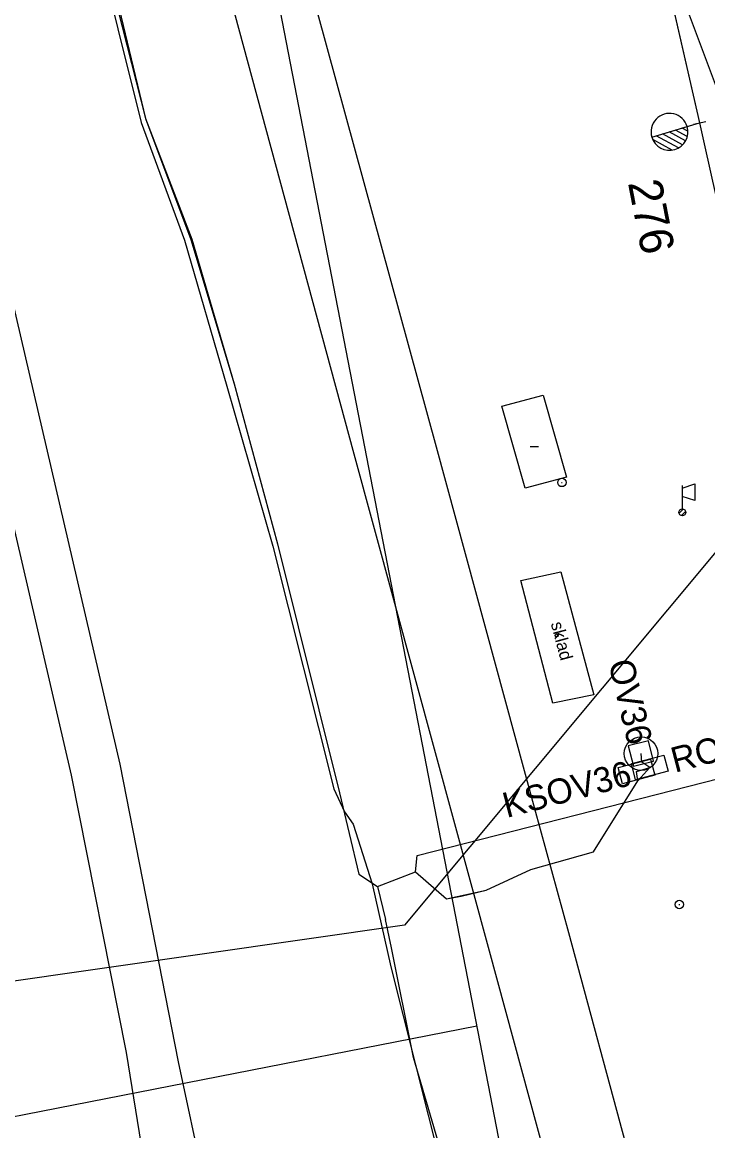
# Model space of a CAD drawing. Extents: x -545846 to -545044, y -1122650 to -1119108.
# Drawn here: x -545637 to -545596.2, y -1119489.2 to -1119423.2 of the extents above; entities that cross this region are included whole.
import ezdxf

# ---------------------------------------------------------------- set-up
doc = ezdxf.new("R2010")
doc.units = 0
for name, color, linetype in [('osvětlené plochy-hodnota-obrys', 7, 'Continuous'), ('Vrstva 1', 7, 'Continuous'), ('Vrstva 12', 7, 'Continuous'), ('Vrstva 12 - Trakce zaklady', 7, 'Continuous'), ('Vrstva 2', 7, 'Continuous'), ('Vrstva 23', 7, 'Continuous'), ('Vrstva 25', 7, 'Continuous'), ('Vrstva 26', 7, 'Continuous'), ('Vrstva 28', 7, 'Continuous'), ('Vrstva 31', 7, 'Continuous'), ('Vrstva 33', 7, 'Continuous'), ('Vrstva 51', 7, 'Continuous'), ('Vrstva 59', 7, 'Continuous'), ('Vrstva 63', 7, 'Continuous')]:
    doc.layers.add(name, color=color, linetype=linetype)

msp = doc.modelspace()

# ---------------------------------------------------------------- linework, layer by layer
at = {"layer": 'osvětlené plochy-hodnota-obrys'}
for points in [[(-545584.854, -1119581.025), (-545603.392, -1119516.801), (-545628.868, -1119385.178)], [(-545609.939, -1119482.977), (-545646.431, -1119490.114), (-545644.897, -1119509.516)]]:
    msp.add_lwpolyline(points, dxfattribs=at)
at = {"layer": 'Vrstva 1'}
for points in [[(-545618.129, -1119370.039), (-545613.658, -1119380.515), (-545613.464, -1119380.986), (-545613.183, -1119381.639), (-545612.962, -1119382.15), (-545612.697, -1119382.765), (-545608.279, -1119393.257), (-545603.774, -1119405.466), (-545603.474, -1119406.246), (-545599.509, -1119416.895), (-545595.059, -1119428.818), (-545593.223, -1119433.873), (-545592.939, -1119434.643), (-545588.997, -1119445.3), (-545584.66, -1119457.036), (-545584.438, -1119457.631), (-545580.06, -1119469.458), (-545575.519, -1119480.71), (-545575.08, -1119481.827), (-545571.114, -1119492.526), (-545565.786, -1119504.472), (-545565.51, -1119505.15), (-545561.154, -1119515.645), (-545556.304, -1119527.336)], [(-545599.509, -1119416.895), (-545596.688, -1119429.205), (-545596.412, -1119430.453), (-545593.934, -1119441.543), (-545591.162, -1119453.963), (-545590.21, -1119458.416), (-545589.948, -1119459.646), (-545584.996, -1119483.934), (-545580.037, -1119509.486), (-545578.326, -1119518.28), (-545575.837, -1119531.038)], [(-545620.215, -1119419.861), (-545619.425, -1119422.675), (-545612.369, -1119448.498), (-545606.521, -1119470.008), (-545604.503, -1119477.399), (-545597.322, -1119503.974), (-545591.579, -1119526.224), (-545589.811, -1119534.529)], [(-545624.755, -1119421.279), (-545624.132, -1119423.572), (-545617.269, -1119448.911), (-545611.272, -1119470.899), (-545609.213, -1119478.484), (-545602.008, -1119504.992), (-545596.298, -1119527.379), (-545594.617, -1119534.889)]]:
    msp.add_lwpolyline(points, dxfattribs=at)
at = {"layer": 'Vrstva 12'}
msp.add_lwpolyline([(-545599.436, -1119467.19), (-545599.726, -1119465.996), (-545600.944, -1119466.286), (-545600.627, -1119467.504), (-545599.436, -1119467.19)], dxfattribs=at)
at = {"layer": 'Vrstva 12 - Trakce zaklady'}
msp.add_lwpolyline([(-545599.436, -1119467.19), (-545599.726, -1119465.996), (-545600.944, -1119466.286), (-545600.627, -1119467.504), (-545599.436, -1119467.19)], dxfattribs=at)
at = {"layer": 'Vrstva 2'}
for p, q in [((-545599.509, -1119416.895), (-545596.688, -1119429.205)), ((-545599.538, -1119430.057), (-545597.434, -1119429.43)), ((-545599.534, -1119430.063), (-545596.688, -1119429.205)), ((-545597.424, -1119430.013), (-545598.123, -1119429.636)), ((-545597.391, -1119429.707), (-545597.736, -1119429.52)), ((-545597.054, -1119429.287), (-545596.322, -1119429.123)), ((-545599.538, -1119430.058), (-545599.538, -1119430.057)), ((-545598.316, -1119430.827), (-545599.484, -1119430.195)), ((-545597.951, -1119430.7), (-545599.281, -1119429.981)), ((-545597.703, -1119430.51), (-545598.895, -1119429.865)), ((-545597.53, -1119430.279), (-545598.509, -1119429.75))]:
    msp.add_line(p, q, dxfattribs=at)
for points in [[(-545603.774, -1119405.466), (-545603.474, -1119406.246), (-545599.509, -1119416.895), (-545595.059, -1119428.818)], [(-545596.688, -1119429.205), (-545596.412, -1119430.453), (-545593.934, -1119441.543), (-545591.162, -1119453.963)]]:
    msp.add_lwpolyline(points, dxfattribs=at)
for centre, radius, start, end in [((-545598.485, -1119429.742), 1.097, 16.55021, 197.01973), ((-545598.485, -1119429.744), 1.098, 196.63974, 16.60059)]:
    msp.add_arc(centre, radius, start, end, dxfattribs=at)
at = {"layer": 'Vrstva 23'}
for points in [[(-545608.452, -1119446.078), (-545605.992, -1119445.422), (-545604.612, -1119450.286), (-545607.07, -1119450.954)], [(-545607.333, -1119456.452), (-545604.947, -1119455.922), (-545602.988, -1119463.245), (-545605.432, -1119463.739)]]:
    msp.add_lwpolyline(points, close=True, dxfattribs=at)
at = {"layer": 'Vrstva 25'}
for points in [[(-545599.611, -1119467.072), (-545599.356, -1119468.039), (-545601.289, -1119468.548), (-545601.544, -1119467.581), (-545599.611, -1119467.072)], [(-545600.499, -1119468.308), (-545600.754, -1119467.341), (-545598.821, -1119466.832), (-545598.566, -1119467.799), (-545600.499, -1119468.308)]]:
    msp.add_lwpolyline(points, dxfattribs=at)
msp.add_circle((-545600.175, -1119466.747), 1, dxfattribs=at)
at = {"layer": 'Vrstva 26'}
for points in [[(-545637.892, -1119393.614), (-545637.617, -1119393.956), (-545636.118, -1119401.068), (-545636.223, -1119402.773), (-545634.694, -1119408.722), (-545634.158, -1119410.258), (-545632.448, -1119418.009), (-545629.669, -1119428.958), (-545626.903, -1119436.124), (-545624.39, -1119444.734), (-545621.805, -1119454.265), (-545618.119, -1119469.086), (-545616.969, -1119473.918), (-545615.854, -1119474.651), (-545615.38, -1119476.622)], [(-545613.606, -1119473.785), (-545613.502, -1119472.802), (-545577.432, -1119463.601), (-545557.746, -1119458.579), (-545557.446, -1119459.448), (-545554.375, -1119463.212), (-545544.393, -1119474.38), (-545535.107, -1119485.279), (-545535.188, -1119486.544), (-545534.523, -1119485.978), (-545528.126, -1119494.269)], [(-545613.502, -1119472.802), (-545577.432, -1119463.601), (-545557.746, -1119458.579)], [(-545615.854, -1119474.651), (-545613.606, -1119473.785), (-545611.748, -1119475.391), (-545610.875, -1119475.225), (-545609.387, -1119474.874), (-545606.731, -1119473.65), (-545603.013, -1119472.594), (-545600.37, -1119468.37), (-545600.45, -1119467.81), (-545599.66, -1119467.57), (-545600.12, -1119467.25), (-545600.175, -1119466.747)], [(-545611.748, -1119475.391), (-545610.875, -1119475.225), (-545609.387, -1119474.874), (-545606.731, -1119473.65), (-545603.013, -1119472.594)], [(-545593.58, -1119580.619), (-545593.117, -1119579.157), (-545592.856, -1119575.399), (-545594.547, -1119566.647), (-545596.344, -1119556.09), (-545599.079, -1119544.096), (-545601.733, -1119531.043), (-545604.88, -1119521.254), (-545606.986, -1119511.352), (-545609.247, -1119502.752), (-545611.596, -1119492.082), (-545613.722, -1119484.832), (-545615.024, -1119478.308), (-545615.38, -1119476.622)]]:
    msp.add_lwpolyline(points, dxfattribs=at)
at = {"layer": 'Vrstva 28'}
for p, q in [((-545604.912, -1119450.61), (-545604.862, -1119450.61)), ((-545597.923, -1119475.728), (-545597.873, -1119475.728))]:
    msp.add_line(p, q, dxfattribs=at)
for centre in [(-545604.887, -1119450.61), (-545597.898, -1119475.728)]:
    msp.add_circle(centre, 0.25, dxfattribs=at)
at = {"layer": 'Vrstva 31'}
for points in [[(-545637.989, -1119391.804), (-545635.985, -1119400.772), (-545634.383, -1119410.231), (-545632.699, -1119418.021), (-545629.919, -1119429.178), (-545627.344, -1119436.193), (-545624.828, -1119444.871), (-545622.088, -1119454.397), (-545618.449, -1119468.848), (-545617.825, -1119470.208), (-545617.305, -1119470.946), (-545616.183, -1119474.502), (-545615.069, -1119479.442), (-545611.368, -1119494.09)], [(-545637.617, -1119393.956), (-545636.118, -1119401.068), (-545636.223, -1119402.773), (-545634.694, -1119408.722), (-545634.158, -1119410.258), (-545629.669, -1119428.958), (-545626.967, -1119436.157), (-545624.39, -1119444.734), (-545621.805, -1119454.265), (-545618.119, -1119469.086), (-545616.969, -1119473.918), (-545615.854, -1119474.651), (-545613.606, -1119473.785), (-545611.748, -1119475.391), (-545609.387, -1119474.874), (-545606.731, -1119473.65), (-545603.013, -1119472.594), (-545600.37, -1119468.37), (-545599.66, -1119467.57)], [(-545615.854, -1119474.651), (-545613.606, -1119473.785), (-545611.748, -1119475.391), (-545610.875, -1119475.225), (-545609.387, -1119474.874), (-545606.731, -1119473.65), (-545603.013, -1119472.594), (-545600.37, -1119468.37), (-545599.66, -1119467.57)]]:
    msp.add_lwpolyline(points, dxfattribs=at)
at = {"layer": 'Vrstva 33'}
for p, q in [((-545597.731, -1119450.94), (-545596.981, -1119450.69)), ((-545597.731, -1119450.79), (-545597.73, -1119452.188)), ((-545596.981, -1119450.69), (-545596.981, -1119451.69)), ((-545596.981, -1119451.69), (-545597.731, -1119451.44)), ((-545597.91, -1119452.443), (-545597.664, -1119452.197)), ((-545597.765, -1119452.582), (-545597.525, -1119452.34))]:
    msp.add_line(p, q, dxfattribs=at)
msp.add_circle((-545597.718, -1119452.388), 0.2, dxfattribs=at)
msp.add_circle((-545597.718, -1119452.388), 0.2, dxfattribs=at)
at = {"layer": 'Vrstva 51'}
for points in [[(-545654.713, -1119405.937), (-545655.51, -1119411.125), (-545652.928, -1119414), (-545647.829, -1119421.354), (-545641.977, -1119434.026), (-545634.094, -1119468.04), (-545630.811, -1119484.542), (-545628.493, -1119498.884), (-545628.199, -1119500.245), (-545627.599, -1119500.06), (-545616.366, -1119546.501)], [(-545654.713, -1119405.937), (-545651.834, -1119408.923), (-545645.293, -1119419.914), (-545639.142, -1119433.19), (-545631.2, -1119467.367), (-545627.715, -1119485.099), (-545624.675, -1119499.385), (-545613.784, -1119545.76)]]:
    msp.add_lwpolyline(points, dxfattribs=at)
at = {"layer": 'Vrstva 59'}
msp.add_line((-545606.781, -1119448.464), (-545606.281, -1119448.464), dxfattribs=at)
msp.add_circle((-545605.202, -1119459.712), 0.0873, dxfattribs=at)
at = {"layer": 'Vrstva 63'}
for p, q in [((-545555.431, -1119406.391), (-545614.243, -1119476.951)), ((-545614.243, -1119476.951), (-545705.196, -1119489.997))]:
    msp.add_line(p, q, dxfattribs=at)

# ---------------------------------------------------------------- texts
at = {"layer": 'Vrstva 2'}
msp.add_text('276', height=2, rotation=281.03148, dxfattribs=at).set_placement((-545600.962, -1119432.771))
at = {"layer": 'Vrstva 23'}
msp.add_text('sklad', height=0.75, rotation=284.9767, dxfattribs=at).set_placement((-545605.555, -1119459.002))
at = {"layer": 'Vrstva 25'}
for s, rotation, p in [('OV36', 283.3925, (-545602.127, -1119461.331)), ('ROV36', 14.76961, (-545598.161, -1119467.89)), ('KSOV36', 14.76961, (-545608.174, -1119470.583))]:
    msp.add_text(s, height=1.5, rotation=rotation, dxfattribs=at).set_placement(p)

doc.saveas('drawing.dxf')
